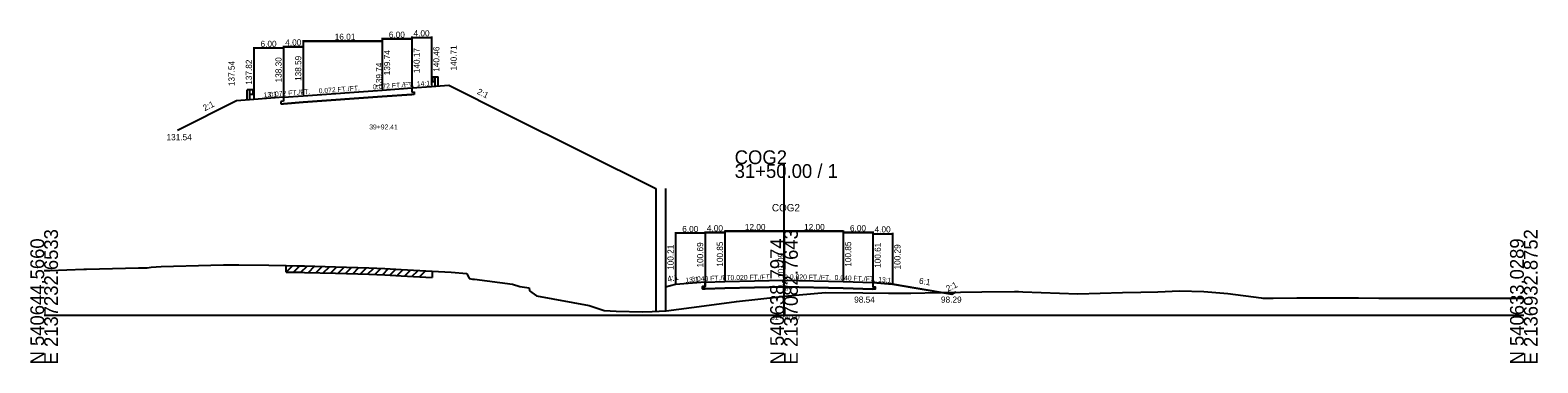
# Model space of a CAD drawing. Extents: x -13397 to 2303, y -10 to 39059.
# Drawn here: x 997.2 to 1302.8, y 2990.3 to 3057.9 of the extents above; entities that cross this region are included whole.
import ezdxf

# ---------------------------------------------------------------- set-up
doc = ezdxf.new("R2010")
doc.units = 0
for name, color, linetype in [('Level 20', 7, 'Continuous'), ('Level 5', 7, 'Continuous'), ('Level 53', 7, 'Continuous'), ('Level 54', 7, 'Continuous'), ('Level 55', 7, 'Continuous'), ('Level 7', 7, 'Continuous'), ('RD_GPK_XS_Cell', 7, 'Continuous'), ('RD_XS_EwShp', 7, 'Continuous'), ('RD_XS_ExGround', 7, 'Continuous'), ('RD_XS_ExPaveRet', 7, 'Continuous'), ('RD_XS_MedBWall', 7, 'Continuous'), ('RD_XS_Pave', 7, 'Continuous'), ('RD_XS_TX_Baseline', 7, 'Continuous'), ('RD_XS_TX_Elev_EX', 7, 'Continuous'), ('RD_XS_TX_Elev_PR', 7, 'Continuous'), ('RD_XS_TX_Station', 7, 'Continuous')]:
    doc.layers.add(name, color=color, linetype=linetype)

msp = doc.modelspace()

# ---------------------------------------------------------------- linework, layer by layer
at = {"layer": 'Level 20'}
for p, q in [((1042.5, 3054.45), (1042.5, 3044.02)), ((1048.5, 3054.25), (1042.5, 3054.25)), ((1048.5, 3054.74), (1048.5, 3044.5)), ((1048.5, 3054.74), (1048.5, 3044.5)), ((1048.5, 3054.74), (1048.5, 3044.5)), ((1048.5, 3054.54), (1052.51, 3054.54)), ((1048.5, 3054.54), (1052.51, 3054.54)), ((1052.51, 3054.54), (1048.5, 3054.54)), ((1048.5, 3054.45), (1048.5, 3044.5)), ((1052.51, 3055.89), (1052.51, 3044.79)), ((1052.51, 3055.89), (1052.51, 3044.79)), ((1052.51, 3055.89), (1052.51, 3044.79)), ((1052.51, 3055.89), (1052.51, 3044.79)), ((1052.51, 3055.69), (1068.51, 3055.69)), ((1052.51, 3055.69), (1068.51, 3055.69)), ((1068.51, 3055.69), (1052.51, 3055.69)), ((1068.51, 3055.69), (1052.51, 3055.69)), ((1052.51, 3054.74), (1052.51, 3044.79)), ((1052.51, 3054.74), (1052.51, 3044.79)), ((1052.51, 3054.74), (1052.51, 3044.79)), ((1068.51, 3056.32), (1068.51, 3045.94)), ((1068.51, 3056.32), (1068.51, 3045.94)), ((1068.51, 3056.32), (1068.51, 3045.94)), ((1068.51, 3056.12), (1074.51, 3056.12)), ((1074.51, 3056.12), (1068.51, 3056.12)), ((1074.51, 3056.12), (1068.51, 3056.12)), ((1068.51, 3055.89), (1068.51, 3045.94)), ((1068.51, 3055.89), (1068.51, 3045.94)), ((1068.51, 3055.89), (1068.51, 3045.94)), ((1068.51, 3055.89), (1068.51, 3045.94)), ((1074.51, 3056.61), (1074.51, 3046.37)), ((1074.51, 3056.41), (1078.52, 3056.41)), ((1074.51, 3056.32), (1074.51, 3046.37)), ((1074.51, 3056.32), (1074.51, 3046.37)), ((1074.51, 3056.32), (1074.51, 3046.37)), ((1078.52, 3056.61), (1078.52, 3046.66)), ((1078.54, 3048.27), (1078.65, 3048.36)), ((1078.54, 3048.17), (1078.65, 3048.08)), ((1078.54, 3047.74), (1078.65, 3047.83)), ((1078.67, 3048.37), (1078.74, 3048.38)), ((1078.67, 3048.03), (1078.67, 3047.88)), ((1078.74, 3048.44), (1078.74, 3047.47)), ((1078.74, 3048.44), (1079.3, 3048.44)), ((1079.3, 3046.46), (1079.3, 3048.44)), ((1079.3, 3048.44), (1079.85, 3048.44)), ((1079.85, 3046.46), (1079.85, 3048.44)), ((1041.16, 3043.82), (1041.16, 3045.81)), ((1041.72, 3045.81), (1041.16, 3045.81)), ((1041.72, 3043.82), (1041.72, 3045.81)), ((1042.28, 3045.81), (1041.72, 3045.81)), ((1042.28, 3044.84), (1041.72, 3044.84)), ((1042.28, 3045.81), (1042.28, 3044.84)), ((1042.35, 3045.74), (1042.28, 3045.75)), ((1042.35, 3044.91), (1042.28, 3044.9)), ((1042.35, 3045.4), (1042.35, 3045.25)), ((1042.48, 3045.64), (1042.36, 3045.73)), ((1042.48, 3045.54), (1042.36, 3045.45)), ((1042.48, 3045.11), (1042.36, 3045.2)), ((1042.48, 3045.01), (1042.36, 3044.92)), ((1048.5, 3044.3), (1052.51, 3044.59)), ((1052.51, 3044.59), (1068.51, 3045.74)), ((1068.51, 3045.74), (1074.51, 3046.17)), ((1074.51, 3044.84), (1068.51, 3044.41)), ((1068.51, 3044.41), (1074.51, 3044.84)), ((1068.51, 3044.41), (1074.51, 3044.84)), ((1074.51, 3046.17), (1078.52, 3046.46)), ((1074.51, 3046.17), (1074.51, 3045.34)), ((1074.51, 3045.34), (1075.01, 3045.37)), ((1075.01, 3044.87), (1074.51, 3044.84)), ((1075.01, 3045.37), (1075.01, 3044.87)), ((1078.52, 3046.46), (1082.02, 3046.71)), ((1078.54, 3047.64), (1078.65, 3047.55)), ((1078.67, 3047.54), (1078.74, 3047.53)), ((1078.74, 3047.47), (1079.3, 3047.47)), ((1082.02, 3046.71), (1094.02, 3040.71)), ((1039, 3043.54), (1027, 3037.54)), ((1042.5, 3043.82), (1039, 3043.54)), ((1048.5, 3044.3), (1042.5, 3043.82)), ((1048.5, 3043.47), (1048, 3043.44)), ((1048, 3043.44), (1048, 3042.94)), ((1048, 3042.94), (1048.5, 3042.97)), ((1048.5, 3044.3), (1048.5, 3043.47)), ((1052.51, 3043.26), (1048.5, 3042.97)), ((1052.51, 3043.26), (1048.5, 3042.97)), ((1048.5, 3042.97), (1052.51, 3043.26)), ((1068.51, 3044.41), (1052.51, 3043.26)), ((1068.51, 3044.41), (1052.51, 3043.26)), ((1052.51, 3043.26), (1068.51, 3044.41)), ((1052.51, 3043.26), (1068.51, 3044.41)), ((1094.02, 3040.71), (1124, 3025.72))]:
    msp.add_line(p, q, dxfattribs=at)
for centre, radius, start, end in [((1078.58, 3048.22), 0.0651, 129.0336, 230.9663), ((1078.58, 3047.69), 0.0651, 129.0336, 230.9663), ((1078.61, 3047.88), 0.0651, 302.9895, 0), ((1078.67, 3048.34), 0.026, 90, 129.0505), ((1078.61, 3048.03), 0.0651, 0, 45), ((1042.35, 3045.71), 0.026, 50.9495, 90), ((1042.41, 3045.4), 0.0651, 135, 180), ((1042.41, 3045.25), 0.0651, 180, 237.0105), ((1042.35, 3044.94), 0.026, 270, 309.0504), ((1042.44, 3045.59), 0.0651, 309.0337, 50.9664), ((1042.44, 3045.06), 0.0651, 309.0337, 50.9664), ((1078.67, 3047.57), 0.026, 230.9496, 270)]:
    msp.add_arc(centre, radius, start, end, dxfattribs=at)
at = {"layer": 'Level 5'}
for p, q in [((1134, 3005.86), (1133.5, 3005.84)), ((1133.5, 3005.84), (1133.5, 3005.34)), ((1133.5, 3005.34), (1134, 3005.36)), ((1134, 3006.69), (1134, 3005.86)), ((1138, 3005.52), (1134, 3005.36)), ((1138, 3005.52), (1134, 3005.36)), ((1138, 3005.52), (1134, 3005.36)), ((1134, 3005.36), (1138, 3005.52)), ((1150, 3005.76), (1138, 3005.52)), ((1150, 3005.76), (1138, 3005.52)), ((1150, 3005.76), (1138, 3005.52)), ((1138, 3005.52), (1150, 3005.76)), ((1138, 3005.52), (1150, 3005.76)), ((1162, 3005.52), (1150, 3005.76)), ((1162, 3005.52), (1150, 3005.76)), ((1150, 3005.76), (1162, 3005.52)), ((1150, 3005.76), (1162, 3005.52)), ((1150, 3005.76), (1162, 3005.52)), ((1168, 3005.28), (1162, 3005.52)), ((1162, 3005.52), (1168, 3005.28)), ((1162, 3005.52), (1168, 3005.28)), ((1162, 3005.52), (1168, 3005.28)), ((1168, 3006.61), (1168, 3005.78)), ((1168, 3005.78), (1168.5, 3005.76)), ((1168.5, 3005.26), (1168, 3005.28)), ((1168.5, 3005.76), (1168.5, 3005.26))]:
    msp.add_line(p, q, dxfattribs=at)
at = {"layer": 'Level 54'}
for p, q in [((1138, 3017.24), (1138, 3007.05)), ((1138, 3017.24), (1138, 3007.05)), ((1138, 3017.24), (1138, 3007.05)), ((1138, 3017.24), (1138, 3007.05)), ((1138, 3017.24), (1138, 3007.05)), ((1150, 3017.24), (1150, 3007.29)), ((1150, 3017.24), (1150, 3007.29)), ((1150, 3017.24), (1150, 3007.29)), ((1150, 3017.24), (1150, 3007.29)), ((1150, 3017.24), (1150, 3007.29)), ((1150, 3017.24), (1150, 3007.29)), ((1150, 3017.24), (1150, 3007.29)), ((1150, 3017.24), (1150, 3007.29)), ((1150, 3017.24), (1150, 3007.29)), ((1150, 3017.24), (1150, 3007.29)), ((1162, 3017.24), (1162, 3007.05)), ((1162, 3017.24), (1162, 3007.05)), ((1162, 3017.24), (1162, 3007.05)), ((1162, 3017.24), (1162, 3007.05)), ((1162, 3017.24), (1162, 3007.05)), ((1128, 3016.84), (1128, 3006.41)), ((1134, 3016.64), (1128, 3016.64)), ((1134, 3017), (1134, 3006.89)), ((1134, 3017), (1134, 3006.89)), ((1134, 3017), (1134, 3006.89)), ((1134, 3017), (1134, 3006.89)), ((1134, 3016.84), (1134, 3006.89)), ((1134, 3016.8), (1138, 3016.8)), ((1134, 3016.8), (1138, 3016.8)), ((1134, 3016.8), (1138, 3016.8)), ((1138, 3016.8), (1134, 3016.8)), ((1138, 3017.04), (1150, 3017.04)), ((1138, 3017.04), (1150, 3017.04)), ((1138, 3017.04), (1150, 3017.04)), ((1150, 3017.04), (1138, 3017.04)), ((1150, 3017.04), (1138, 3017.04)), ((1138, 3017), (1138, 3007.05)), ((1138, 3017), (1138, 3007.05)), ((1138, 3017), (1138, 3007.05)), ((1138, 3017), (1138, 3007.05)), ((1150, 3017.04), (1162, 3017.04)), ((1150, 3017.04), (1162, 3017.04)), ((1162, 3017.04), (1150, 3017.04)), ((1162, 3017.04), (1150, 3017.04)), ((1162, 3017.04), (1150, 3017.04)), ((1162, 3017), (1162, 3007.05)), ((1162, 3017), (1162, 3007.05)), ((1162, 3017), (1162, 3007.05)), ((1162, 3017), (1162, 3007.05)), ((1162, 3016.8), (1168, 3016.8)), ((1168, 3016.8), (1162, 3016.8)), ((1168, 3016.8), (1162, 3016.8)), ((1168, 3016.8), (1162, 3016.8)), ((1168, 3017), (1168, 3006.81)), ((1168, 3017), (1168, 3006.81)), ((1168, 3017), (1168, 3006.81)), ((1168, 3017), (1168, 3006.81)), ((1168, 3016.76), (1168, 3006.81)), ((1168, 3016.56), (1172, 3016.56)), ((1172, 3016.76), (1172, 3006.49))]:
    msp.add_line(p, q, dxfattribs=at)
at = {"layer": 'Level 7'}
for p, q in [((1128, 3006.21), (1126, 3005.71)), ((1126, 3005.71), (1126, 3000.9)), ((1134, 3006.69), (1128, 3006.21)), ((1168, 3006.61), (1172, 3006.29)), ((1172, 3006.29), (1184, 3004.29)), ((1184, 3004.29), (1184.8, 3004.69))]:
    msp.add_line(p, q, dxfattribs=at)
at = {"layer": 'RD_GPK_XS_Cell'}
for p, q in [((1150, 3000), (1150, 3030.69)), ((1000, 3000), (1150, 3000)), ((1150, 3000), (1300, 3000))]:
    msp.add_line(p, q, dxfattribs=at)
at = {"layer": 'RD_XS_EwShp'}
for points in [[(1165.98, 3004.55), (1171.19, 3004.47), (1175.71, 3004.47), (1181.47, 3004.64), (1181.87, 3004.64), (1172, 3006.29), (1168, 3006.61), (1168, 3005.78), (1168.5, 3005.76), (1168.5, 3005.26), (1168, 3005.28), (1162, 3005.52), (1150, 3005.76), (1138, 3005.52), (1134, 3005.36), (1133.5, 3005.34), (1133.5, 3005.84), (1134, 3005.86), (1134, 3006.69), (1128, 3006.21), (1126, 3005.71), (1126, 3000.9), (1126.12, 3000.9), (1133.81, 3001.89), (1140.38, 3002.75), (1149.66, 3003.83), (1150, 3003.85), (1158.41, 3004.58)], [(1181.87, 3004.64), (1184.8, 3004.69), (1184, 3004.29)]]:
    msp.add_lwpolyline(points, close=True, dxfattribs=at)
at = {"layer": 'RD_XS_ExGround'}
for p, q in [((1000, 3009.05), (1001.12, 3009.08)), ((1001.12, 3009.08), (1008.04, 3009.33)), ((1008.04, 3009.33), (1008.57, 3009.34)), ((1008.57, 3009.34), (1019.1, 3009.6)), ((1019.1, 3009.6), (1020.88, 3009.6)), ((1020.88, 3009.6), (1021.67, 3009.75)), ((1021.67, 3009.75), (1023.74, 3009.88)), ((1023.74, 3009.88), (1033.81, 3010.16)), ((1033.81, 3010.16), (1036.38, 3010.23)), ((1036.38, 3010.23), (1039.48, 3010.22)), ((1039.48, 3010.22), (1045.58, 3010.19)), ((1045.58, 3010.19), (1049.07, 3010.07)), ((1049.07, 3010.07), (1051.25, 3010.03)), ((1051.25, 3010.03), (1052.14, 3010.02)), ((1052.14, 3010.02), (1052.77, 3010)), ((1052.77, 3010), (1059.05, 3009.82)), ((1059.05, 3009.82), (1065.82, 3009.62)), ((1065.82, 3009.62), (1069.07, 3009.51)), ((1069.07, 3009.51), (1072.39, 3009.29)), ((1072.39, 3009.29), (1078.69, 3008.94)), ((1078.69, 3008.94), (1079.92, 3008.86)), ((1079.92, 3008.86), (1082.5, 3008.73)), ((1082.5, 3008.73), (1085.68, 3008.47)), ((1085.68, 3008.47), (1086.16, 3007.46)), ((1086.16, 3007.46), (1086.87, 3007.3)), ((1086.87, 3007.3), (1087.24, 3007.34)), ((1087.24, 3007.34), (1094.95, 3006.31)), ((1094.95, 3006.31), (1096.47, 3005.84)), ((1096.47, 3005.84), (1098.33, 3005.54)), ((1098.33, 3005.54), (1098.41, 3004.97)), ((1098.41, 3004.97), (1099.79, 3003.95)), ((1225.78, 3004.73), (1230.19, 3004.95)), ((1230.19, 3004.95), (1235.11, 3004.81)), ((1099.79, 3003.95), (1110.48, 3001.99)), ((1110.48, 3001.99), (1113.51, 3000.95)), ((1126.12, 3000.9), (1133.81, 3001.89)), ((1133.81, 3001.89), (1140.38, 3002.75)), ((1140.38, 3002.75), (1149.66, 3003.83)), ((1149.66, 3003.83), (1150, 3003.85)), ((1150, 3003.85), (1158.41, 3004.58)), ((1158.41, 3004.58), (1165.98, 3004.55)), ((1165.98, 3004.55), (1171.19, 3004.47)), ((1171.19, 3004.47), (1175.71, 3004.47)), ((1175.71, 3004.47), (1181.47, 3004.64)), ((1181.47, 3004.64), (1190.13, 3004.77)), ((1190.13, 3004.77), (1196.76, 3004.83)), ((1196.76, 3004.83), (1197.54, 3004.83)), ((1197.54, 3004.83), (1198.45, 3004.74)), ((1198.45, 3004.74), (1209.54, 3004.33)), ((1209.54, 3004.33), (1218.61, 3004.61)), ((1218.61, 3004.61), (1222.33, 3004.65)), ((1222.33, 3004.65), (1225.78, 3004.73)), ((1235.11, 3004.81), (1240.01, 3004.43)), ((1240.01, 3004.43), (1246.77, 3003.51)), ((1246.77, 3003.51), (1247.11, 3003.44)), ((1247.11, 3003.44), (1249.16, 3003.44)), ((1249.16, 3003.44), (1253.96, 3003.54)), ((1253.96, 3003.54), (1266, 3003.5)), ((1266, 3003.5), (1266.47, 3003.51)), ((1266.47, 3003.51), (1270.57, 3003.44)), ((1270.57, 3003.44), (1274.84, 3003.44)), ((1274.84, 3003.44), (1281.49, 3003.44)), ((1281.49, 3003.44), (1296.08, 3003.44)), ((1296.08, 3003.44), (1296.97, 3003.45)), ((1296.97, 3003.45), (1300, 3003.46)), ((1113.51, 3000.95), (1115.98, 3000.82)), ((1115.98, 3000.82), (1121.28, 3000.67)), ((1121.28, 3000.67), (1123.3, 3000.78)), ((1123.3, 3000.78), (1126.12, 3000.9))]:
    msp.add_line(p, q, dxfattribs=at)
at = {"layer": 'RD_XS_ExPaveRet'}
for p, q in [((1049.07, 3008.77), (1049.07, 3010.07)), ((1049.07, 3008.77), (1050.34, 3010.05)), ((1049.07, 3008.77), (1051.25, 3008.73)), ((1050.57, 3008.74), (1051.84, 3010.02)), ((1051.25, 3008.73), (1052.14, 3008.72)), ((1052.07, 3008.72), (1053.33, 3009.98)), ((1052.14, 3008.72), (1052.77, 3008.7)), ((1052.77, 3008.7), (1059.05, 3008.52)), ((1053.57, 3008.68), (1054.83, 3009.94)), ((1055.07, 3008.63), (1056.33, 3009.9)), ((1056.57, 3008.59), (1057.83, 3009.85)), ((1058.07, 3008.54), (1059.33, 3009.81)), ((1059.05, 3008.52), (1065.82, 3008.32)), ((1059.57, 3008.5), (1060.83, 3009.76)), ((1061.07, 3008.46), (1062.33, 3009.72)), ((1062.57, 3008.41), (1063.83, 3009.67)), ((1064.07, 3008.37), (1065.33, 3009.63)), ((1065.57, 3008.32), (1066.83, 3009.58)), ((1065.82, 3008.32), (1069.07, 3008.21)), ((1067.07, 3008.28), (1068.33, 3009.54)), ((1068.57, 3008.23), (1069.8, 3009.47)), ((1069.07, 3008.21), (1072.39, 3007.99)), ((1070.07, 3008.15), (1071.28, 3009.36)), ((1071.57, 3008.05), (1072.79, 3009.27)), ((1072.39, 3007.99), (1078.69, 3007.64)), ((1073.07, 3007.95), (1074.3, 3009.18)), ((1074.57, 3007.87), (1075.8, 3009.1)), ((1076.07, 3007.78), (1077.3, 3009.01)), ((1078.69, 3008.94), (1078.69, 3007.64))]:
    msp.add_line(p, q, dxfattribs=at)
at = {"layer": 'RD_XS_MedBWall'}
for p, q in [((1124, 3025.72), (1124, 3000.81)), ((1126, 3025.72), (1126, 3005.71))]:
    msp.add_line(p, q, dxfattribs=at)
at = {"layer": 'RD_XS_Pave'}
for p, q in [((1134, 3006.69), (1138, 3006.85)), ((1138, 3006.85), (1150, 3007.09)), ((1150, 3007.09), (1162, 3006.85)), ((1162, 3006.85), (1168, 3006.61))]:
    msp.add_line(p, q, dxfattribs=at)

# ---------------------------------------------------------------- texts
at = {"layer": 'Level 20'}
for s, height, p in [('16.01', 1.25, (1058.91, 3055.94)), ('16.01', 1.25, (1058.91, 3055.94)), ('16.01', 1.25, (1058.91, 3055.94)), ('16.01', 1.25, (1058.91, 3055.94)), ('6.00', 1.25, (1069.88, 3056.37)), ('6.00', 1.25, (1069.88, 3056.37)), ('6.00', 1.25, (1069.88, 3056.37)), ('4.00', 1.25, (1074.89, 3056.66)), ('6.00', 1.25, (1043.87, 3054.5)), ('4.00', 1.25, (1048.88, 3054.79)), ('4.00', 1.25, (1048.88, 3054.79)), ('4.00', 1.25, (1048.88, 3054.79)), ('39+92.41', 1, (1065.9, 3037.74)), ('131.54', 1.25, (1024.81, 3035.54))]:
    msp.add_text(s, height=height, dxfattribs=at).set_placement(p)
for s, height, rotation, p in [('139.74', 1.25, 90, (1070.14, 3048.74)), ('139.74', 1.25, 90, (1070.14, 3048.74)), ('140.17', 1.25, 90, (1076.14, 3049.17)), ('140.46', 1.25, 90, (1080.14, 3049.46)), ('140.71', 1.25, 90, (1083.64, 3049.71)), ('137.54', 1.25, 90, (1038.62, 3046.54)), ('137.82', 1.25, 90, (1042.13, 3046.82)), ('138.30', 1.25, 90, (1048.13, 3047.3)), ('138.59', 1.25, 90, (1052.13, 3047.59)), ('138.59', 1.25, 90, (1052.13, 3047.59)), (' 139.74', 1.25, 90, (1068.51, 3045.74)), ('14:1', 1, 4.0972, (1075.6, 3046.5)), ('13:1', 1, 4.5721, (1044.53, 3044.24)), ('0.072 FT./FT.', 1, 4.098, (1045.68, 3044.35)), ('0.072 FT./FT.', 1, 4.098, (1045.68, 3044.35)), ('0.072 FT./FT.', 1, 4.098, (1045.68, 3044.35)), ('0.072 FT./FT.', 1, 4.0983, (1055.69, 3045.07)), ('0.072 FT./FT.', 1, 4.0983, (1055.69, 3045.07)), ('0.072 FT./FT.', 1, 4.0983, (1055.69, 3045.07)), ('0.072 FT./FT.', 1, 4.0983, (1055.69, 3045.07)), ('0.072 FT./FT.', 1, 4.0987, (1066.69, 3045.86)), ('0.072 FT./FT.', 1, 4.0987, (1066.69, 3045.86)), ('0.072 FT./FT.', 1, 4.0987, (1066.69, 3045.86)), ('2:1', 1.25, 333.4436, (1087.63, 3045.02)), ('2:1', 1.25, 26.556, (1032.55, 3041.44))]:
    msp.add_text(s, height=height, rotation=rotation, dxfattribs=at).set_placement(p)
at = {"layer": 'Level 53'}
for s, rotation, p in [('100.21', 90, (1127.62, 3009.21)), ('100.69', 90, (1133.62, 3009.69)), ('100.85', 90, (1137.63, 3009.85)), ('100.85', 90, (1137.63, 3009.85)), ('100.85', 90, (1137.63, 3009.85)), ('100.85', 90, (1163.62, 3009.85)), ('100.85', 90, (1163.62, 3009.85)), ('100.85', 90, (1163.62, 3009.85)), ('100.61', 90, (1169.62, 3009.61)), ('100.29', 90, (1173.62, 3009.29)), ('4:1', 14.0362, (1126.5, 3006.68)), ('6:1', 350.5377, (1177.3, 3006.42))]:
    msp.add_text(s, height=1.25, rotation=rotation, dxfattribs=at).set_placement(p)
for s, p in [('98.54', (1164.23, 3002.54)), ('98.29', (1181.83, 3002.54))]:
    msp.add_text(s, height=1.25, dxfattribs=at).set_placement(p)
at = {"layer": 'Level 54'}
for s, p in [('6.00', (1129.37, 3016.89)), ('4.00', (1134.37, 3017.05)), ('4.00', (1134.37, 3017.05)), ('4.00', (1134.37, 3017.05)), ('4.00', (1134.37, 3017.05)), ('12.00', (1142.07, 3017.29)), ('12.00', (1142.07, 3017.29)), ('12.00', (1142.07, 3017.29)), ('12.00', (1142.07, 3017.29)), ('12.00', (1142.07, 3017.29)), ('12.00', (1154.07, 3017.29)), ('12.00', (1154.07, 3017.29)), ('12.00', (1154.07, 3017.29)), ('12.00', (1154.07, 3017.29)), ('12.00', (1154.07, 3017.29)), ('6.00', (1163.37, 3017.05)), ('6.00', (1163.37, 3017.05)), ('6.00', (1163.37, 3017.05)), ('6.00', (1163.37, 3017.05)), ('4.00', (1168.37, 3016.81))]:
    msp.add_text(s, height=1.25, dxfattribs=at).set_placement(p)
at = {"layer": 'Level 55'}
for s, height, rotation, p in [('0.040 FT./FT.', 1, 2.2906, (1131.22, 3006.83)), ('0.040 FT./FT.', 1, 2.2906, (1131.22, 3006.83)), ('0.040 FT./FT.', 1, 2.2906, (1131.22, 3006.83)), ('0.040 FT./FT.', 1, 2.2906, (1131.22, 3006.83)), ('0.020 FT./FT.', 1, 1.1458, (1139.17, 3007.12)), ('0.020 FT./FT.', 1, 1.1458, (1139.17, 3007.12)), ('0.020 FT./FT.', 1, 1.1458, (1139.17, 3007.12)), ('0.020 FT./FT.', 1, 1.1458, (1139.17, 3007.12)), ('0.020 FT./FT.', 1, 1.1458, (1139.17, 3007.12)), ('0.020 FT./FT.', 1, 358.8542, (1151.18, 3007.32)), ('0.020 FT./FT.', 1, 358.8542, (1151.18, 3007.32)), ('0.020 FT./FT.', 1, 358.8542, (1151.18, 3007.32)), ('0.020 FT./FT.', 1, 358.8542, (1151.18, 3007.32)), ('0.020 FT./FT.', 1, 358.8542, (1151.18, 3007.32)), ('0.040 FT./FT.', 1, 357.7094, (1160.24, 3007.17)), ('0.040 FT./FT.', 1, 357.7094, (1160.24, 3007.17)), ('0.040 FT./FT.', 1, 357.7094, (1160.24, 3007.17)), ('0.040 FT./FT.', 1, 357.7094, (1160.24, 3007.17)), ('13:1', 1, 4.5739, (1130.03, 3006.62)), ('13:1', 1, 355.4261, (1169.07, 3006.78)), ('2:1', 1.25, 26.5651, (1183.22, 3004.74))]:
    msp.add_text(s, height=height, rotation=rotation, dxfattribs=at).set_placement(p)
at = {"layer": 'RD_GPK_XS_Cell'}
for s, p in [('COG2', (1140, 3030.69)), ('31+50.00 / 1', (1140, 3027.89))]:
    msp.add_text(s, height=2.8, dxfattribs=at).set_placement(p)
for s, p in [('E 2137232.6533', (1002.8, 2990)), ('E 2137082.7643', (1152.8, 2990)), ('E 2136932.8752', (1302.8, 2990)), ('N 540644.5660', (1000, 2990)), ('N 540638.7974', (1150, 2990)), ('N 540633.0289', (1300, 2990))]:
    msp.add_text(s, height=2.8, rotation=90, dxfattribs=at).set_placement(p)
at = {"layer": 'RD_XS_TX_Baseline'}
msp.add_text('COG2', height=1.5, dxfattribs=at).set_placement((1147.55, 3021.09))
at = {"layer": 'RD_XS_TX_Elev_EX'}
msp.add_text('97.85', height=1, rotation=90, dxfattribs=at).set_placement((1150.75, 3004.85))
at = {"layer": 'RD_XS_TX_Elev_PR'}
msp.add_text(' 101.09', height=1.25, rotation=90, dxfattribs=at).set_placement((1150, 3007.09))
at = {"layer": 'RD_XS_TX_Station'}
msp.add_text('31+50.00', height=1, dxfattribs=at).set_placement((1147.36, 2999.09))

doc.saveas('drawing.dxf')
